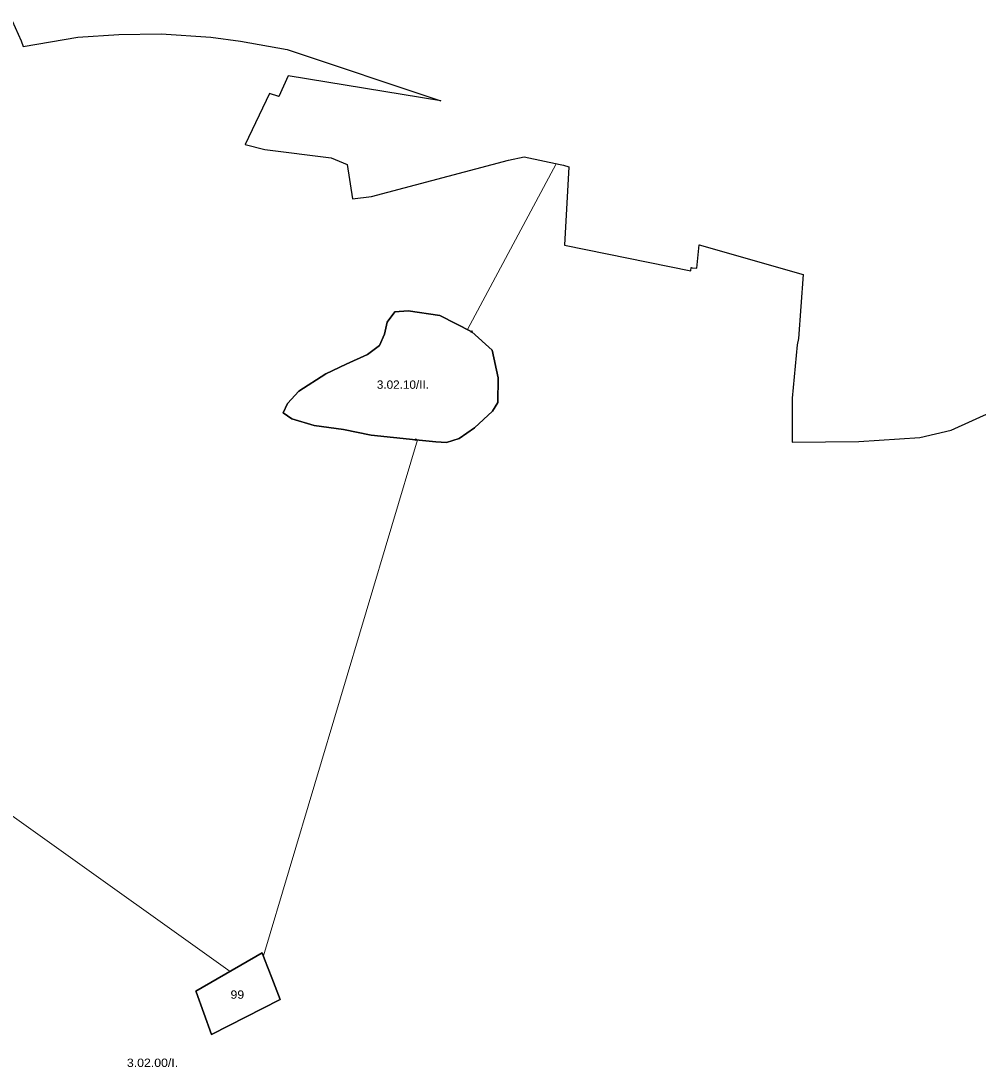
# Model space of a CAD drawing. Extents: x -650455 to -642254, y -1075222 to -1066610.
# Drawn here: x -647688 to -646541, y -1068519 to -1067266 of the extents above; entities that cross this region are included whole.
import ezdxf
from ezdxf.enums import TextEntityAlignment as Align

# ---------------------------------------------------------------- set-up
doc = ezdxf.new("R2010")
doc.units = 0
doc.header["$LTSCALE"] = 4
doc.header["$PDMODE"] = 32
doc.header["$PDSIZE"] = 2
for name, color, linetype, lineweight in [('1', 7, 'Continuous', 25), ('11', 7, 'Continuous', 13), ('12', 7, 'Continuous', 13)]:
    doc.layers.add(name, color=color, linetype=linetype, lineweight=lineweight)
doc.layers.add('2', color=7, linetype='Continuous')

msp = doc.modelspace()

# ---------------------------------------------------------------- linework, layer by layer
at = {"layer": '1'}
for points in [[(-647698.194, -1067265.832), (-647687.428, -1067289.554), (-647687.308, -1067289.546), (-647684.69, -1067296.31), (-647619.38, -1067285.2), (-647570.47, -1067281.951), (-647519.4, -1067281.471), (-647459.92, -1067285.471), (-647424.4, -1067290.04), (-647368.76, -1067299.86)], [(-647368.76, -1067299.86), (-647184.77, -1067361.597), (-647367.518, -1067331.619), (-647378.524, -1067356.191), (-647390.02, -1067352.83), (-647418.82, -1067413.95), (-647395.37, -1067419.621), (-647315.89, -1067429.711), (-647296.75, -1067437.911), (-647290.23, -1067478.891), (-647267.49, -1067476.231), (-647103.55, -1067432.541), (-647084.77, -1067428.64), (-647084.677, -1067428.646), (-647041.702, -1067437.89), (-647037.69, -1067438.599), (-647031.34, -1067440.67), (-647036.59, -1067534.22), (-646885.13, -1067564.9), (-646884.641, -1067561.022), (-646883.481, -1067561.494), (-646877.8, -1067561.778), (-646875.016, -1067533.934), (-646750.479, -1067569.325), (-646756.307, -1067646.28), (-646757.65, -1067653.671), (-646763.84, -1067717.631), (-646763.64, -1067770.23), (-646684.13, -1067769.34), (-646610.97, -1067764.461), (-646573.28, -1067755.921), (-646522.089, -1067732.688)]]:
    msp.add_lwpolyline(points, dxfattribs=at)
for points in [[(-647190.741, -1067769.669), (-647177.946, -1067770.455), (-647162.788, -1067765.732), (-647144.284, -1067753.035), (-647122.631, -1067733.152), (-647116.528, -1067722.917), (-647115.938, -1067693.192), (-647123.024, -1067660.022), (-647147.631, -1067637.976), (-647185.623, -1067618.487), (-647223.615, -1067613.073), (-647239.757, -1067614.256), (-647248.812, -1067626.656), (-647252.158, -1067640.83), (-647258.064, -1067654.609), (-647272.631, -1067665.239), (-647298.024, -1067676.951), (-647322.434, -1067688.369), (-647354.52, -1067709.136), (-647368.103, -1067724.097), (-647373.418, -1067735.121), (-647363.182, -1067742.208), (-647336.213, -1067750.278), (-647301.371, -1067755.2), (-647268.103, -1067761.696), (-647214.56, -1067767.307)], [(-647162.788, -1067765.732), (-647177.946, -1067770.455), (-647190.741, -1067769.669), (-647214.56, -1067767.307), (-647268.103, -1067761.696), (-647301.371, -1067755.2), (-647336.213, -1067750.278), (-647363.182, -1067742.208), (-647373.418, -1067735.121), (-647368.103, -1067724.097), (-647354.52, -1067709.136), (-647322.434, -1067688.369), (-647298.024, -1067676.951), (-647272.631, -1067665.239), (-647258.064, -1067654.609), (-647252.158, -1067640.83), (-647248.812, -1067626.656), (-647239.757, -1067614.256), (-647223.615, -1067613.073), (-647185.623, -1067618.487), (-647147.631, -1067637.976), (-647123.024, -1067660.022), (-647115.938, -1067693.192), (-647116.528, -1067722.917), (-647122.631, -1067733.152), (-647144.284, -1067753.035)], [(-647376.86, -1068437.7), (-647459.108, -1068479.58), (-647477.732, -1068428.347), (-647477.925, -1068427.816), (-647398.64, -1068381.751), (-647395.77, -1068389.131), (-647386.94, -1068411.821)], [(-647398.64, -1068381.751), (-647477.925, -1068427.816), (-647477.732, -1068428.347), (-647459.108, -1068479.58), (-647376.86, -1068437.7), (-647386.94, -1068411.821), (-647395.77, -1068389.131)]]:
    msp.add_lwpolyline(points, close=True, dxfattribs=at)
at = {"layer": '11'}
for points in [[(-647459.92, -1067285.471), (-647519.4, -1067281.471), (-647570.47, -1067281.951), (-647619.38, -1067285.2), (-647684.69, -1067296.31), (-647687.308, -1067289.546), (-647687.428, -1067289.554), (-647698.194, -1067265.832)], [(-647892.553, -1068079.303), (-647436.972, -1068404.022), (-647398.64, -1068381.751), (-647397.191, -1068385.476), (-647212.703, -1067767.491), (-647214.56, -1067767.307), (-647268.103, -1067761.696), (-647301.371, -1067755.2), (-647336.213, -1067750.278), (-647363.182, -1067742.208), (-647373.418, -1067735.121), (-647368.103, -1067724.097), (-647354.52, -1067709.136), (-647322.434, -1067688.369), (-647298.024, -1067676.951), (-647272.631, -1067665.239), (-647258.064, -1067654.609), (-647252.158, -1067640.83), (-647248.812, -1067626.656), (-647239.757, -1067614.256), (-647223.615, -1067613.073), (-647185.623, -1067618.487), (-647152.562, -1067635.447), (-647046.5, -1067436.858), (-647084.677, -1067428.646), (-647084.77, -1067428.64), (-647103.55, -1067432.541), (-647267.49, -1067476.231), (-647290.23, -1067478.891), (-647296.75, -1067437.911), (-647315.89, -1067429.711), (-647395.37, -1067419.621), (-647418.82, -1067413.95), (-647390.02, -1067352.83), (-647378.524, -1067356.191), (-647367.518, -1067331.619), (-647184.77, -1067361.597), (-647368.76, -1067299.86), (-647424.4, -1067290.04), (-647459.92, -1067285.471)], [(-646522.089, -1067732.688), (-646573.28, -1067755.921), (-646610.97, -1067764.461), (-646684.13, -1067769.34), (-646763.64, -1067770.23), (-646763.84, -1067717.631), (-646757.65, -1067653.671), (-646756.307, -1067646.28), (-646750.479, -1067569.325), (-646875.016, -1067533.934), (-646877.8, -1067561.778), (-646883.481, -1067561.494), (-646884.641, -1067561.022), (-646885.13, -1067564.9), (-647036.59, -1067534.22), (-647031.34, -1067440.67), (-647037.69, -1067438.599), (-647041.702, -1067437.89), (-647046.5, -1067436.858), (-647152.562, -1067635.447), (-647147.631, -1067637.976), (-647123.024, -1067660.022), (-647115.938, -1067693.192), (-647116.528, -1067722.917), (-647122.631, -1067733.152), (-647144.284, -1067753.035), (-647162.788, -1067765.732), (-647177.946, -1067770.455), (-647190.741, -1067769.669), (-647212.703, -1067767.491), (-647397.191, -1068385.476), (-647395.77, -1068389.131), (-647386.94, -1068411.821), (-647376.86, -1068437.7), (-647459.108, -1068479.58), (-647477.732, -1068428.347), (-647477.925, -1068427.816), (-647436.972, -1068404.022), (-647892.553, -1068079.303)]]:
    msp.add_lwpolyline(points, dxfattribs=at)
at = {"layer": '12'}
for points in [[(-647147.631, -1067637.976), (-647152.562, -1067635.447), (-647185.623, -1067618.487), (-647223.615, -1067613.073), (-647239.757, -1067614.256), (-647248.812, -1067626.656), (-647252.158, -1067640.83), (-647258.064, -1067654.609), (-647272.631, -1067665.239), (-647298.024, -1067676.951), (-647322.434, -1067688.369), (-647354.52, -1067709.136), (-647368.103, -1067724.097), (-647373.418, -1067735.121), (-647363.182, -1067742.208), (-647336.213, -1067750.278), (-647301.371, -1067755.2), (-647268.103, -1067761.696), (-647214.56, -1067767.307)], [(-647214.56, -1067767.307), (-647190.741, -1067769.669), (-647177.946, -1067770.455), (-647162.788, -1067765.732), (-647144.284, -1067753.035), (-647122.631, -1067733.152), (-647116.528, -1067722.917), (-647115.938, -1067693.192), (-647123.024, -1067660.022), (-647147.631, -1067637.976)]]:
    msp.add_lwpolyline(points, dxfattribs=at)
for p in [(-647147.631, -1067637.976), (-647214.56, -1067767.307)]:
    msp.add_point(p, dxfattribs=at)

# ---------------------------------------------------------------- texts
at = {"layer": '2'}
for s, width, p in [('3.02.10/II.', 1.05, (-647230.025, -1067706.333)), ('99', 1.1, (-647428.378, -1068436.711)), ('3.02.00/I.', 1.1, (-647529.932, -1068518.388))]:
    msp.add_text(s, height=10, dxfattribs=dict(at, width=width)).set_placement(p, align=Align.CENTER)

doc.saveas('drawing.dxf')
